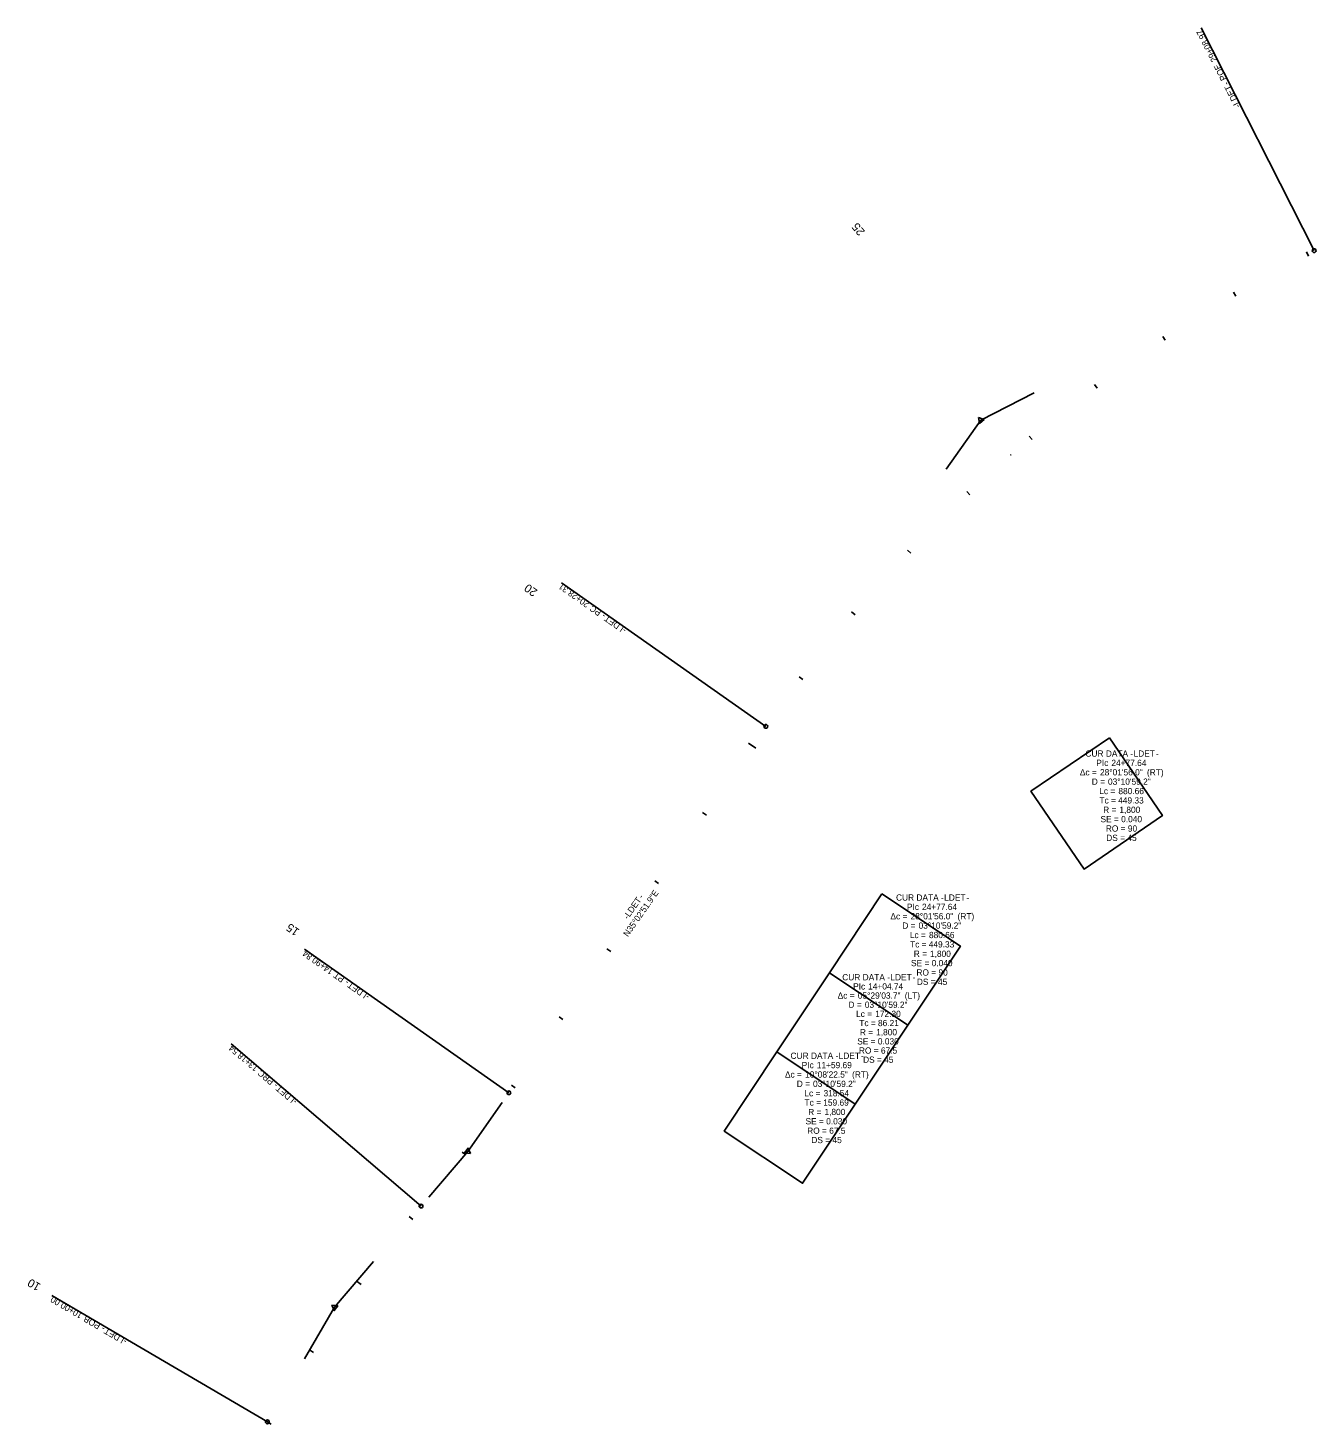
# Model space of a CAD drawing. Extents: x 2379684 to 2381232, y 331642 to 333319.
import ezdxf

# ---------------------------------------------------------------- set-up
doc = ezdxf.new("R2010")
doc.units = 0
for name, color, linetype in [('_CIVIL_CONSTRUCTION', 7, 'Continuous'), ('Default', 7, 'Continuous'), ('P_NCDOT_Horizontal_Alignment', 7, 'Continuous'), ('P_NCDOT_Horizontal_Alignment_Direction_Label', 7, 'Continuous'), ('P_NCDOT_Horizontal_Alignment_Station_Label', 7, 'Continuous'), ('P_NCDOT_Horizontal_Alignment_Station_Major_Label', 7, 'Continuous'), ('P_NCDOT_Horizontal_Alignment_Tick_Large', 7, 'Continuous'), ('P_NCDOT_Horizontal_Alignment_Tick_Small', 7, 'Continuous')]:
    doc.layers.add(name, color=color, linetype=linetype)

msp = doc.modelspace()

# ---------------------------------------------------------------- linework, layer by layer
at = {"layer": 'Default'}
for p, q in [((2380828.9, 332847.7), (2380893.1, 332880.3)), ((2380828.9, 332847.7), (2380787.5, 332788.7)), ((2380828.9, 332847.7), (2380828.9, 332847.7)), ((2380212.7, 331969.2), (2380254, 332028.2)), ((2380212.7, 331969.2), (2380165.9, 331914.5)), ((2380212.7, 331969.2), (2380212.7, 331969.2)), ((2380052.9, 331782.3), (2380099.7, 331837.1)), ((2380052.9, 331782.3), (2380016.5, 331720.2)), ((2380052.9, 331782.3), (2380052.9, 331782.3))]:
    msp.add_line(p, q, dxfattribs=at)
for points in [[(2380826.1, 332850.8), (2380827.5, 332843.7), (2380832.9, 332848.5)], [(2380216, 331966.7), (2380213.2, 331973.3), (2380208.8, 331967.6)], [(2380049.5, 331784.7), (2380052.5, 331778.2), (2380056.7, 331784.1)]]:
    msp.add_lwpolyline(points, close=True, dxfattribs=at)
at = {"layer": 'P_NCDOT_Horizontal_Alignment'}
for p, q in [((2381220.3, 333049.5), (2381222.8, 333044.6)), ((2381132.5, 333001.2), (2381135.3, 332996.5)), ((2381047.6, 332948.2), (2381050.6, 332943.6)), ((2380965.7, 332890.5), (2380969, 332886.1)), ((2380887.2, 332828.4), (2380890.7, 332824.2)), ((2380812.2, 332762), (2380816, 332758)), ((2380741, 332691.5), (2380745, 332687.7)), ((2380673.9, 332617.3), (2380678.1, 332613.7)), ((2380611, 332539.3), (2380615.4, 332536)), ((2380494.9, 332376.4), (2380499.4, 332373.2)), ((2380437.5, 332294.5), (2380442, 332291.3)), ((2380380, 332212.6), (2380384.6, 332209.4)), ((2380322.6, 332130.8), (2380327.1, 332127.6)), ((2380265.2, 332048.9), (2380269.7, 332045.7)), ((2380206, 331968.5), (2380210.3, 331965.1)), ((2380142.6, 331891.3), (2380146.8, 331887.8)), ((2380080.4, 331812.8), (2380084.9, 331809.5)), ((2380022.8, 331730.9), (2380027.4, 331727.9))]:
    msp.add_line(p, q, dxfattribs=at)
at = {"layer": 'P_NCDOT_Horizontal_Alignment_Direction_Label'}
for points in [[(2380983.5, 332466.1), (2381047.2, 332372.6), (2380953, 332308.4), (2380889.3, 332401.9)], [(2380710.3, 332278.6), (2380804.5, 332215.9), (2380741.3, 332121), (2380647.1, 332183.7)], [(2380647.1, 332183.7), (2380741.3, 332121), (2380678.1, 332026.1), (2380584, 332088.8)], [(2380584, 332088.8), (2380678.1, 332026.1), (2380615, 331931.2), (2380520.8, 331993.8)]]:
    msp.add_lwpolyline(points, close=True, dxfattribs=at)
at = {"layer": 'P_NCDOT_Horizontal_Alignment_Station_Major_Label'}
for p, q in [((2381229.5, 333051.1), (2381093.7, 333318.6)), ((2380570.8, 332479.8), (2380325.2, 332652.1)), ((2380262.2, 332039.8), (2380016.6, 332212.1)), ((2380156.7, 331903.7), (2379928.6, 332098.7)), ((2379972.1, 331644.6), (2379713.3, 331796.4))]:
    msp.add_line(p, q, dxfattribs=at)
for centre in [(2381229.5, 333051.1), (2380570.8, 332479.8), (2380262.2, 332039.8), (2380156.7, 331903.7), (2379972.1, 331644.6)]:
    msp.add_circle(centre, 2.25, dxfattribs=at)
at = {"layer": 'P_NCDOT_Horizontal_Alignment_Tick_Large'}
for centre in [(2380865.1, 332805.9), (2379972.1, 331644.6)]:
    msp.add_circle(centre, 0.05, dxfattribs=at)
at = {"layer": 'P_NCDOT_Horizontal_Alignment_Tick_Small'}
for p, q in [((2380550.2, 332459.7), (2380558.9, 332453.6)), ((2379967.5, 331647.3), (2379976.6, 331641.9))]:
    msp.add_line(p, q, dxfattribs=at)

# ---------------------------------------------------------------- texts
at = {"layer": '_CIVIL_CONSTRUCTION'}
for s, rotation, p in [('25', 129.5852, (2380690.4, 333074.2)), ('20', 144.9522, (2380297.4, 332643.1)), ('15', 144.5997, (2380011.5, 332235.3)), ('10', 149.6068, (2379700.7, 331809.6))]:
    msp.add_text(s, height=10, rotation=rotation, dxfattribs=at).set_placement(p)
at = {"layer": 'P_NCDOT_Horizontal_Alignment_Direction_Label'}
for s, p in [('CUR DATA -', (2380954.7, 332443.4)), ('LDET', (2381012.5, 332443.4)), ('PIc ', (2380967.8, 332432.2)), ('24+77.64', (2380985.9, 332432.2)), ('-', (2381039.3, 332443.4)), ('Δc = ', (2380948, 332420.9)), ('D = ', (2380962.3, 332409.7)), ('28°01\'56.0"', (2380972.2, 332420.9)), ('03°10\'59.2"', (2380981.8, 332409.7)), (' (RT)', (2381025.8, 332420.9)), ('Lc = ', (2380971.3, 332398.4)), ('880.66', (2380994.3, 332398.4)), ('Tc = ', (2380971.6, 332387.2)), ('R = ', (2380976, 332375.9)), ('449.33', (2380994, 332387.2)), ('1,800', (2380995.5, 332375.9)), ('SE = 0.040', (2380972.8, 332364.7)), ('RO = 90', (2380979.2, 332353.4)), ('DS = 45', (2380979.7, 332342.2)), ('CUR DATA -', (2380727.2, 332270.5)), ('PIc ', (2380740.3, 332259.3)), ('24+77.64', (2380758.4, 332259.3)), ('LDET', (2380785, 332270.5)), ('-', (2380811.8, 332270.5)), ('Δc = ', (2380720.5, 332248)), ('28°01\'56.0"', (2380744.7, 332248)), (' (RT)', (2380798.3, 332248)), ('D = ', (2380734.8, 332236.8)), ('Lc = ', (2380743.8, 332225.5)), ('03°10\'59.2"', (2380754.3, 332236.8)), ('880.66', (2380766.8, 332225.5)), ('Tc = ', (2380744.1, 332214.3)), ('449.33', (2380766.5, 332214.3)), ('SE = 0.040', (2380745.2, 332191.8)), ('R = ', (2380748.5, 332203)), ('1,800', (2380768, 332203)), ('CUR DATA -', (2380662.6, 332174.8)), ('LDET', (2380720.4, 332174.8)), ('RO = 90', (2380751.7, 332180.5)), ('PIc ', (2380675.7, 332163.8)), ('14+04.74', (2380693.7, 332163.8)), ('-', (2380747.2, 332174.8)), ('DS = 45', (2380752.2, 332169.3)), ('Δc = ', (2380657.1, 332152.8)), ('D = ', (2380670.1, 332141.8)), ('05°29\'03.7"', (2380681.3, 332152.8)), ('03°10\'59.2"', (2380689.7, 332141.8)), (' (LT)', (2380734.9, 332152.8)), ('Lc = ', (2380679.2, 332130.8)), ('172.30', (2380702.2, 332130.8)), ('Tc = ', (2380683.1, 332119.8)), ('R = ', (2380683.8, 332108.8)), ('1,800', (2380703.3, 332108.8)), ('86.21', (2380705.5, 332119.8)), ('SE = 0.030', (2380680.6, 332097.8)), ('CUR DATA -', (2380600.5, 332080.5)), ('LDET', (2380658.3, 332080.5)), ('RO = 67.5', (2380682.6, 332086.8)), ('-', (2380685.1, 332080.5)), ('DS = 45', (2380687.6, 332075.8)), ('Δc = ', (2380593.8, 332058)), ('PIc ', (2380613.9, 332069.3)), ('10°08\'22.5"', (2380618, 332058)), ('11+59.69', (2380632, 332069.3)), (' (RT)', (2380671.6, 332058)), ('D = ', (2380608, 332046.8)), ('03°10\'59.2"', (2380627.5, 332046.8)), ('Tc = ', (2380617.3, 332024.3)), ('Lc = ', (2380617.1, 332035.5)), ('318.54', (2380640.1, 332035.5)), ('159.69', (2380639.8, 332024.3)), ('R = ', (2380621.7, 332013)), ('1,800', (2380641.2, 332013)), ('SE = 0.030', (2380618.5, 332001.8)), ('RO = 67.5', (2380620.5, 331990.5)), ('DS = 45', (2380625.5, 331979.3))]:
    msp.add_text(s, height=7.5, dxfattribs=at).set_placement(p)
at = {"layer": 'P_NCDOT_Horizontal_Alignment_Station_Label'}
for s, p in [('N35°02\'51.9"E', (2380405.1, 332226.5)), ('LDET', (2380407.1, 332250.3)), ('-', (2380422.5, 332272.2)), ('-', (2380405.1, 332247.4))]:
    msp.add_text(s, height=7.5, rotation=54.9522, dxfattribs=at).set_placement(p)
at = {"layer": 'P_NCDOT_Horizontal_Alignment_Station_Major_Label'}
for s, rotation, p in [('29+08.97', 116.92, (2381113.4, 333279.8)), ('POE', 116.92, (2381124.7, 333257.5)), ('LDET', 116.92, (2381139.7, 333227.9)), ('- ', 116.92, (2381127.6, 333251.8)), ('-', 116.92, (2381141.3, 333224.8)), ('20+28.31', 144.9522, (2380359.7, 332627.9)), ('PC', 144.9522, (2380374, 332617.9)), ('- ', 144.9522, (2380379.2, 332614.2)), ('LDET', 144.9522, (2380401.1, 332598.9)), ('-', 144.9522, (2380404, 332596.8)), ('14+90.84', 144.9522, (2380052.2, 332187.1)), ('PT', 144.9522, (2380065.5, 332177.8)), ('- ', 144.9522, (2380070.8, 332174.1)), ('LDET', 144.9522, (2380092.7, 332158.7)), ('-', 144.9522, (2380095.5, 332156.7)), ('13+18.54', 139.4679, (2379961.7, 332070.4)), ('PRC', 139.4679, (2379980.7, 332054.1)), ('- ', 139.4679, (2379985.6, 332050)), ('LDET', 139.4679, (2380005.9, 332032.6)), ('-', 139.4679, (2380008.6, 332030.3)), ('10+00.00', 149.6068, (2379750.8, 331774.4)), ('POB', 149.6068, (2379772.4, 331761.7)), ('- ', 149.6068, (2379777.9, 331758.5)), ('LDET', 149.6068, (2379801, 331744.9)), ('-', 149.6068, (2379804.1, 331743.2))]:
    msp.add_text(s, height=7.5, rotation=rotation, dxfattribs=at).set_placement(p)

doc.saveas('drawing.dxf')
